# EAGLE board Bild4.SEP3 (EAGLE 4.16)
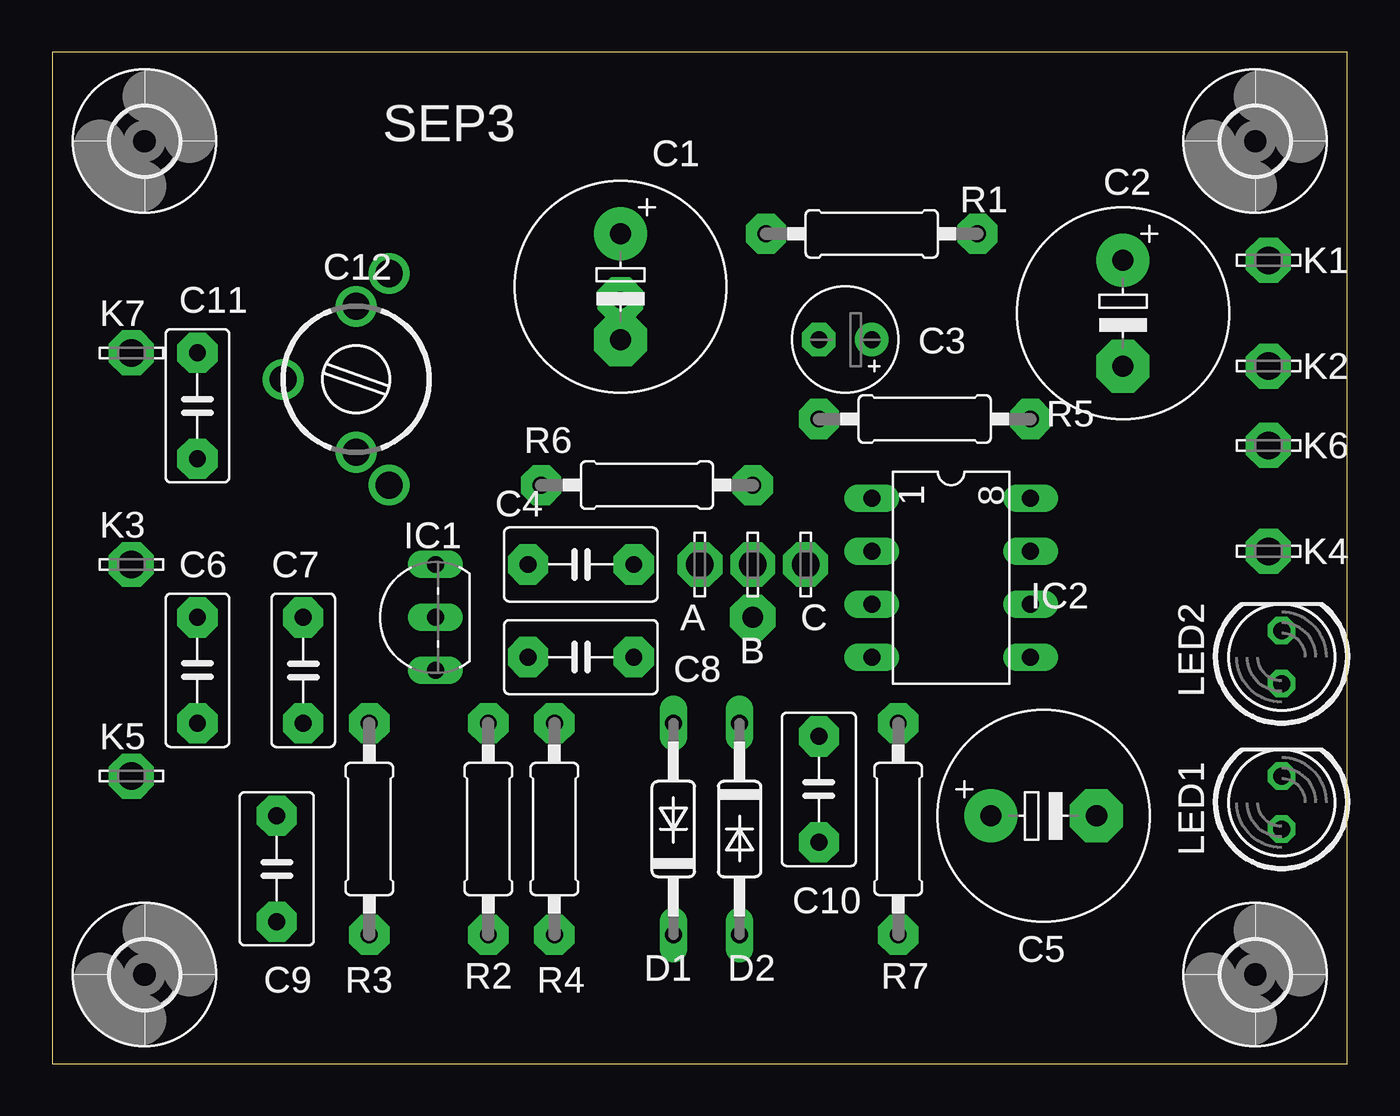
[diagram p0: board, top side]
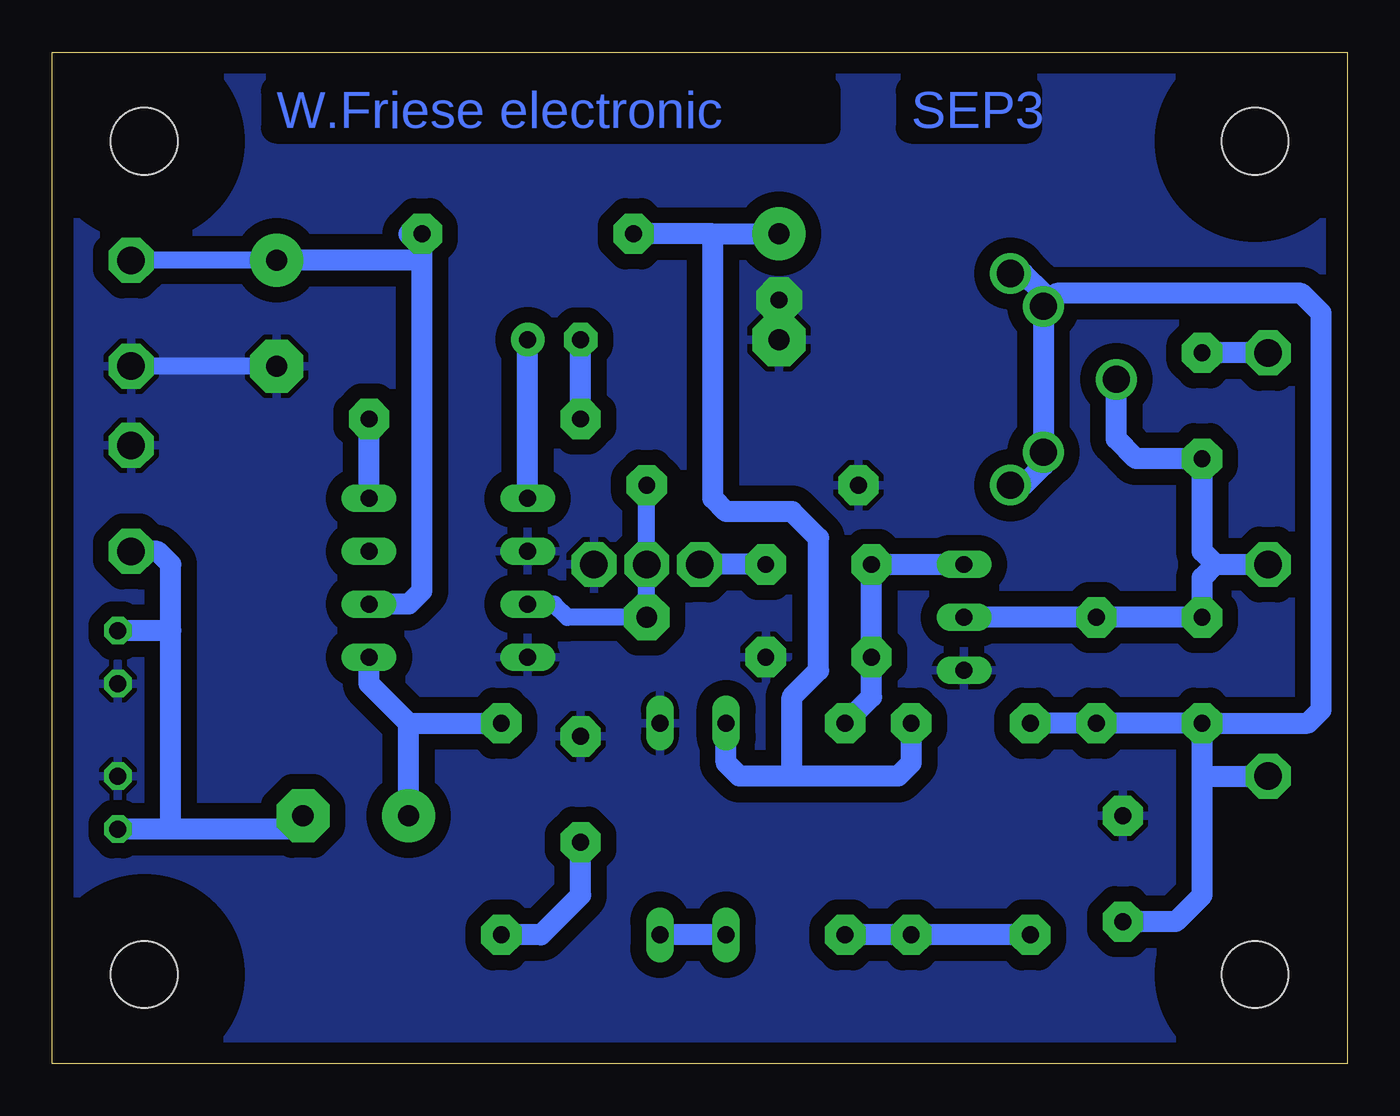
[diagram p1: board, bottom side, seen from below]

Size 62.21 x 48.56 mm. Coordinates in mm from the lower left corner, seen from the top.
Outline: 0,0 62.21,0 62.21,48.56 0,48.56 0,0
Copper layers 16: Bottom 0.035mm
Design rules "default": minimum track width 10mil, minimum drill 24mil, track to track 8mil, track to pad 8mil, pad to pad 8mil, via to via 8mil, smd to smd 8mil, copper to edge 40mil, drill to drill 8mil, minimum pad ring 10mil, minimum via ring 8mil, stop-mask expansion 0mil, vias tented up to drill 0mil, thermal gap 10mil

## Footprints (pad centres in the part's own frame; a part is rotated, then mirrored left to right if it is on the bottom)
LSP13 = drill 1.321 pad 2.159 octagon: MP 0,0
E5-10,5 = drill 1.016 pad 2.54 round: + -2.54,0 | drill 1.016 pad 2.54 octagon: - 2.54,0
E2,5-5 = drill 0.813 pad 1.6 round: + -1.27,0 | drill 0.813 pad 1.6 octagon: - 1.27,0
C050-035X075 = drill 0.813 pad 1.93 octagon: 1 -2.54,0; 2 2.54,0
C050-030X075 = drill 0.813 pad 1.93 octagon: 1 -2.54,0; 2 2.54,0
CTRIM3040.427 = drill 1.3 round: 1A -3.5,0; 1B 3.5,0; 2 0,-3.5
DO35-10 = drill 0.813 long: A 5.08,0; C -5.08,0
3,2 = hole 3.2: 0,0
TO92 = drill 0.813 long: 1 -2.54,0; 2 0,0; 3 2.54,0
DIL08@1 = drill 0.813 long: 1 -3.81,-3.81; 2 -1.27,-3.81; 3 1.27,-3.81; 4 3.81,-3.81; 5 3.81,3.81; 6 1.27,3.81; 7 -1.27,3.81; 8 -3.81,3.81
LED5MM = drill 0.813 octagon: A -1.27,0; K 1.27,0
0207/10E = drill 0.813 pad 1.93 octagon: 1 -4.445,0; 2 5.715,0

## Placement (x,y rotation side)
A  LSP13  [LSP13]  31.11,23.96 90 top
B  LSP13  [LSP13]  33.65,23.96 90 top
C  LSP13  [LSP13]  36.19,23.96 270 top
C1  [E5-10,5]  27.3,37.3 270 top
C2  [E5-10,5]  51.43,36.03 270 top
C3  [E2,5-5]  38.09,34.76 180 top
C4  [C050-035X075]  25.39,23.96 0 top
C5  [E5-10,5]  47.62,11.9 0 top
C6  [C050-030X075]  6.98,18.89 90 top
C7  [C050-030X075]  12.06,18.89 270 top
C8  [C050-035X075]  25.39,19.52 0 top
C9  [C050-035X075]  10.79,9.36 270 top
C10  [C050-035X075]  36.82,13.17 90 top
C11  [C050-030X075]  6.98,31.59 270 top
C12  [CTRIM3040.427]  14.6,32.86 270 top
D1  [DO35-10]  29.84,11.27 90 top
D2  [DO35-10]  33.02,11.27 270 top
H1  MOUNT-HOLE3.2  [3,2]  4.44,4.28 0 top
H2  MOUNT-HOLE3.2  [3,2]  57.78,44.29 0 top
H3  MOUNT-HOLE3.2  [3,2]  57.78,4.28 0 top
H4  MOUNT-HOLE3.2  [3,2]  4.44,44.29 0 top
IC1  MK484  [TO92]  18.41,21.43 90 top
IC2  [DIL08@1]  43.17,23.33 270 top
K1  LSP13  [LSP13]  58.41,38.57 0 top
K2  LSP13  [LSP13]  58.41,33.49 0 top
K3  LSP13  [LSP13]  3.81,23.96 0 top
K4  LSP13  [LSP13]  58.41,24.6 0 top
K5  LSP13  [LSP13]  3.81,13.81 0 top
K6  LSP13  [LSP13]  58.41,29.68 0 top
K7  LSP13  [LSP13]  3.81,34.12 0 top
LED1  [LED5MM]  59.05,12.54 90 top
LED2  [LED5MM]  59.05,19.52 90 top
R1  [0207/10E]  40,39.84 180 top
R2  [0207/10E]  20.95,11.9 270 top
R3  [0207/10E]  15.23,10.63 90 top
R4  [0207/10E]  24.12,10.63 90 top
R5  [0207/10E]  41.27,30.95 0 top
R6  [0207/10E]  29.21,27.78 180 top
R7  [0207/10E]  40.63,11.9 270 top

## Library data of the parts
A B C K1-K7 = solpad
C1-C12 R1-R7 = rcl
D1 D2 = diode
H1-H4 = holes
IC1 = FMW
IC2 = linear
LED1 LED2 = led

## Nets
GND: C1.- C2.- C8.2 C9.1 C10.2 C.MP D2.C IC1.1 IC2.2 IC2.4 K2.MP K6.MP LED1.K LED2.A R6.2
N$1: C2.+ IC2.6 K1.MP R1.1
N$2: C6.2 C7.1 C11.2 C12.2 IC1.2 K3.MP
N$3: D1.C D2.A
N$4: C4.1 C8.1 IC1.3 R4.2
N$5: C3.+ IC2.1
N$6: C3.- R5.1
N$7: C11.1 K7.MP
N$8: R2.2 R3.1 R4.1
N$9: IC2.8 R5.2
N$10: C1.+ D1.A R1.2 R2.1
N$11: A.MP C4.2
N$12: C5.+ IC2.5 R7.1
N$13: B.MP IC2.3 R6.1
N$15: C5.- K4.MP LED1.A LED2.K
N$18: C6.1 C7.2 C9.2 C12.1A K5.MP R3.2
N$23: C10.1 R7.2

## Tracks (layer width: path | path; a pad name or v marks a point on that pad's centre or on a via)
GND  (via drill 0.8 pad 2.18)
  Bottom 0.813: C2.- K2.MP
  other vias: 27.3,36.66
  pour Bottom (isolate 0.75): -0.01,48.73 -0.01,-0.17 62.22,-0.17 62.22,48.73
N$1
  Bottom 0.813: C2.+ K1.MP
  Bottom 1.016: 44.45,38.57 C2.+ | 44.45,38.57 R1.1 45.08,39.84 44.45,39.2 44.45,38.57 | IC2.6 45.08,22.06 44.45,22.7 44.45,38.57
N$2
  Bottom 1.016: IC1.2 C7.1 C6.2 6.98,23.33 6.34,23.96 | 6.34,23.96 K3.MP | 6.34,23.96 6.98,24.6 C11.2 10.15,29.05 11.1,29.99 C12.2
N$3
  Bottom 1.016: D1.C D2.A
N$4
  Bottom 1.016: IC1.3 C4.1 C8.1 22.86,17.62 R4.2
N$5
  Bottom 1.016: IC2.1 C3.+
N$6
  Bottom 1.016: R5.1 C3.-
N$7
  Bottom 1.016: K7.MP C11.1
N$8
  Bottom 1.016: R4.1 R2.2 R3.1
N$9
  Bottom 1.016: IC2.8 R5.2
N$10
  Bottom 1.016: 30.48,39.84 R1.2 | R2.1 20.95,14.44 21.59,13.81 26.67,13.81 | 26.67,13.81 29.21,13.81 29.84,14.44 D1.A | 30.48,39.84 C1.+ | 30.48,39.84 30.48,27.14 29.84,26.51 26.67,26.51 25.39,25.23 25.39,18.89 26.67,17.62 26.67,13.81
N$11
  Bottom 1.016: C4.2 A.MP
N$12
  Bottom 1.016: IC2.5 46.98,18.25 45.08,16.35 | C5.+ 45.08,16.35 | 45.08,16.35 R7.1
N$13  (via drill 1 pad 2.18)
  Bottom 0.813: R6.1 B.MP v33.65,21.43 37.46,21.43 38.09,22.06 IC2.3
N$15
  Bottom 1.016: C5.- 50.79,11.27 56.51,11.27 | 56.51,11.27 LED1.A | 56.51,11.27 56.51,20.79 | 56.51,20.79 56.51,23.96 57.14,24.6 K4.MP | 56.51,20.79 LED2.K
N$18  (via drill 1.3)
  Bottom 1.016: C6.1 C7.2 R3.2 | 6.98,13.81 C6.1 | 6.98,13.81 K5.MP | C9.2 8.25,6.82 6.98,8.09 6.98,13.81 | C12.1A | C12.1A 14.6,36.98 15.55,37.94 v16.19,37.94 | C12.1A 14.6,28.73 15.55,27.78 v16.19,27.78 | C6.1 1.9,16.35 1.27,16.98 1.27,36.03 2.22,36.98 13.96,36.98 C12.1A
N$23
  Bottom 1.016: R7.2 38.73,6.18 36.82,8.09 C10.1

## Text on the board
Bottom: SEP3 | W.Friese electronic
tPlace: SEP3
_tNames: C1 | R1 | C2 | C12 | K1 | K7 | C11 | C3 | K2 | R5 | R6 | K6 | IC1 | C4 | K3 | K4 | C6 | C7 | A | IC2 | B | C | C8 | LED2 | K5 | LED1 | C10 | R3 | R4 | D1 | C5 | C9 | R2 | D2 | R7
